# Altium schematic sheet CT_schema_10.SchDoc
size 226 x 144 mm
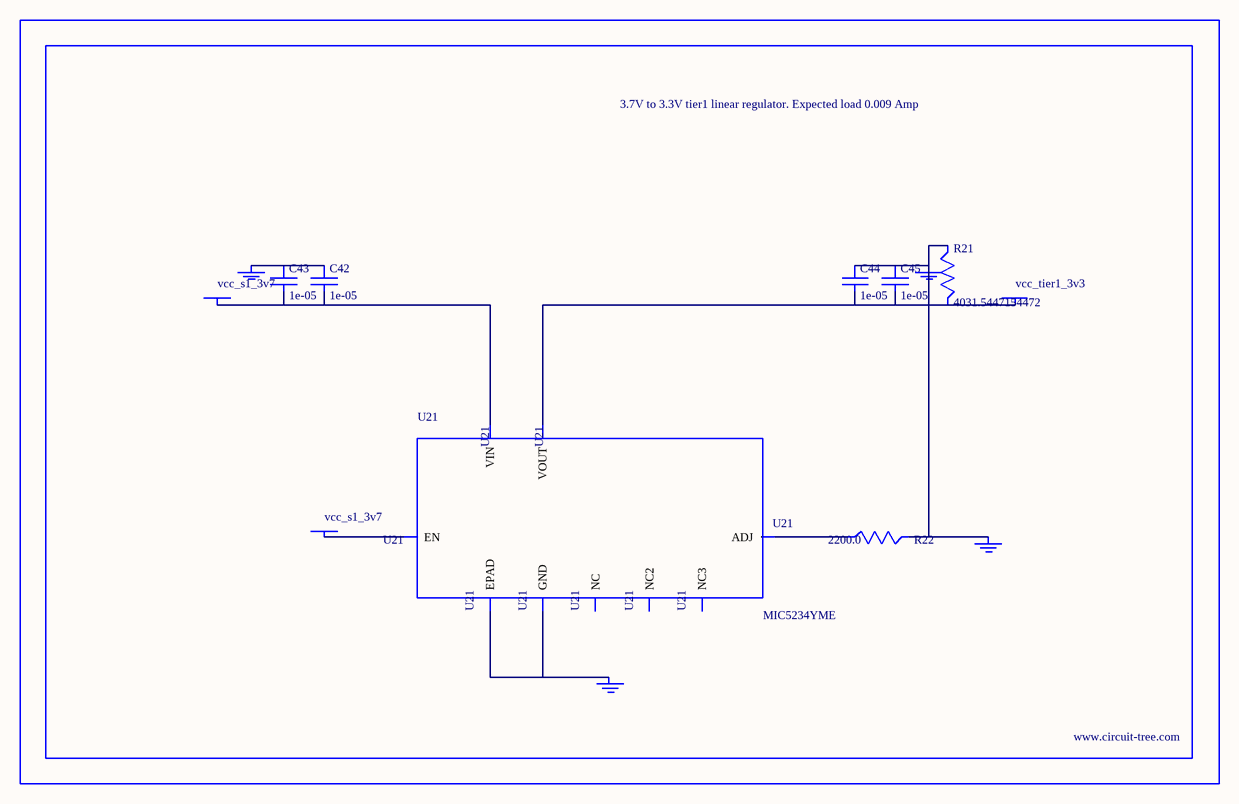
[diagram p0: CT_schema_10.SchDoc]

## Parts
BORDER9  (no value)
C42  1e-05  [C1210]
C43  1e-05  [C1210]
C44  1e-05  [C1210]
C45  1e-05  [C1210]
GND_INSTANCE_9_0  (no value)
GND_INSTANCE_9_1  (no value)
GND_INSTANCE_9_2  (no value)
GND_INSTANCE_9_3  (no value)
POWER_INSTANCE_9_0  vcc_tier1_3v3
POWER_INSTANCE_9_1  vcc_s1_3v7
POWER_INSTANCE_9_2  vcc_s1_3v7
R21  4031.5447154472  [R0603]
R22  2200.0  [R0603]
U21  MIC5234YME  [SOIC-8_EP]

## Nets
NetC42_1: C42.1 C43.1 GND_INSTANCE_9_3.0(GND)
NetC42_2: C42.2 C43.2 POWER_INSTANCE_9_2.0(PWR) U21.8(VIN)
NetC44_1: C44.1 C45.1 GND_INSTANCE_9_0.0(GND) GND_INSTANCE_9_1.0(GND) R21.1 R22.2
NetC44_2: C44.2 C45.2 POWER_INSTANCE_9_0.0(PWR) R21.2 U21.1(VOUT)
NetGND_INSTANCE_9_2_0: GND_INSTANCE_9_2.0(GND) U21.7(GND) U21.EPAD
NetPOWER_INSTANCE_9_1_0: POWER_INSTANCE_9_1.0(PWR) U21.5(EN)
NetR22_1: R22.1 U21.4(ADJ)

Not connected (* = marked no-connect by the designer): U21 2(NC) 3(NC2) 6(NC3)

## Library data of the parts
BORDER9 = BORDER_PAGE9
C42-C45 = C1210C106K5PACTU
GND_INSTANCE_9_0-GND_INSTANCE_9_3 = GND
POWER_INSTANCE_9_0-POWER_INSTANCE_9_2 = PWR
R21 = R21
R22 = RC0603JR-072K2L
